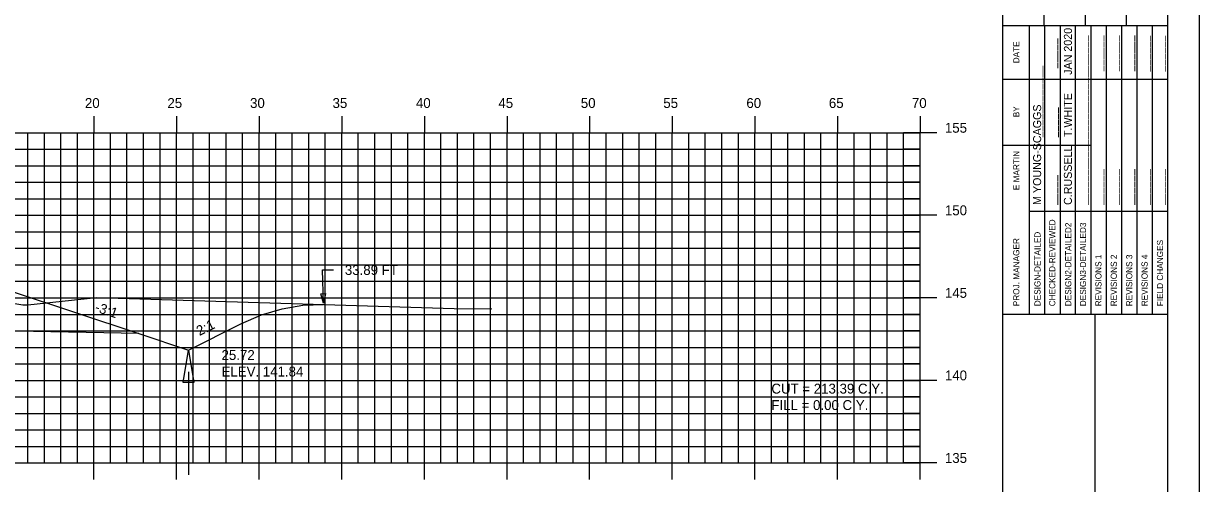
# Model space of a CAD drawing. Extents: x 1144751 to 1144921, y 608981 to 609091.
# Drawn here: x 1144849.4 to 1144920.5, y 609019.1 to 609047 of the extents above; entities that cross this region are included whole.
import ezdxf

# ---------------------------------------------------------------- set-up
doc = ezdxf.new("R2010")
doc.units = 0
for name, color, linetype in [('ANNOTATION', 7, 'Continuous'), ('BORDER', 7, 'Continuous'), ('D_Drainage_Ditch_Line', 7, 'Continuous'), ('D_Roadway_SlopeLines', 7, 'Continuous'), ('D_Roadway_SubGrade', 7, 'Continuous'), ('D_Text_Standard', 7, 'Continuous'), ('H_V ANNOTATION', 7, 'Continuous'), ('MAJOR', 7, 'Continuous'), ('MINOR', 7, 'Continuous'), ('PLOT BOUNDARY', 7, 'Continuous'), ('S_Roadway_Centerline', 7, 'Continuous')]:
    doc.layers.add(name, color=color, linetype=linetype)

msp = doc.modelspace()

# ---------------------------------------------------------------- linework, layer by layer
msp.add_lwpolyline([(1144816.245, 609030.888), (1144818.619, 609030.746), (1144822.619, 609030.906), (1144833.619, 609031.126), (1144844.619, 609030.906), (1144848.619, 609030.746), (1144856.342, 609028.171), (1144859.342, 609027.171), (1144862.514, 609028.757), (1144863.764, 609029.299), (1144865.014, 609029.675), (1144866.264, 609029.885), (1144867.514, 609029.928)])
at = {"layer": 'BORDER'}
for p, q in [((1144908.619, 608984.335), (1144908.619, 609089.335)), ((1144911.119, 609046.838), (1144911.119, 609055.485)), ((1144913.619, 609046.838), (1144913.619, 609055.485)), ((1144916.119, 609046.838), (1144916.119, 609055.485)), ((1144908.619, 609046.838), (1144918.619, 609046.838)), ((1144908.619, 609029.338), (1144918.619, 609029.338)), ((1144914.21, 608994.338), (1144914.21, 609029.338))]:
    msp.add_line(p, q, dxfattribs=at)
msp.add_lwpolyline([(1144758.619, 608984.335), (1144918.619, 608984.335), (1144918.619, 609089.335), (1144758.619, 609089.335)], close=True, dxfattribs=at)
for points in [[(1144910.234, 609043.588), (1144910.234, 609046.838)], [(1144911.167, 609029.341), (1144911.167, 609046.838)], [(1144912.098, 609046.838), (1144912.098, 609029.341)], [(1144913.03, 609029.341), (1144913.03, 609046.838)], [(1144913.962, 609029.341), (1144913.962, 609046.838)], [(1144914.893, 609029.341), (1144914.893, 609046.838)], [(1144915.825, 609029.341), (1144915.825, 609046.838)], [(1144916.757, 609029.341), (1144916.757, 609046.838)], [(1144917.688, 609029.341), (1144917.688, 609046.838)], [(1144910.235, 609029.341), (1144910.235, 609046.132)], [(1144908.619, 609043.588), (1144918.619, 609043.588)], [(1144908.619, 609039.588), (1144910.235, 609039.588)], [(1144910.234, 609039.588), (1144913.961, 609039.588)], [(1144910.234, 609035.588), (1144918.619, 609035.588)]]:
    msp.add_lwpolyline(points, dxfattribs=at)
at = {"layer": 'D_Drainage_Ditch_Line'}
msp.add_line((1144859.342, 609025.859), (1144859.342, 609019.616), dxfattribs=at)
msp.add_lwpolyline([(1144859.67, 609025.203), (1144859.014, 609025.203), (1144859.342, 609027.171)], close=True, dxfattribs=at)
at = {"layer": 'D_Roadway_SlopeLines'}
for points in [[(1144859.342, 609027.171), (1144862.514, 609028.757), (1144863.764, 609029.299), (1144865.014, 609029.675), (1144866.264, 609029.885), (1144867.514, 609029.928)], [(1144856.342, 609028.171), (1144859.342, 609027.171)]]:
    msp.add_lwpolyline(points, dxfattribs=at)
at = {"layer": 'D_Roadway_SubGrade'}
msp.add_lwpolyline([(1144844.619, 609030.489), (1144844.619, 609030.656), (1144848.619, 609030.496), (1144848.619, 609030.746), (1144848.619, 609030.746), (1144856.342, 609028.171), (1144844.619, 609028.406)], close=True, dxfattribs=at)
at = {"layer": 'D_Text_Standard'}
msp.add_lwpolyline([(1144867.514, 609030.007), (1144867.445, 609032.022), (1144868.125, 609032.022)], dxfattribs=at)
msp.add_lwpolyline([(1144867.514, 609030.007), (1144867.348, 609030.584), (1144867.639, 609030.594)], close=True, dxfattribs=at)
at = {"layer": 'MAJOR'}
for p, q in [((1144853.619, 609041.337), (1144853.619, 609040.335)), ((1144858.619, 609041.337), (1144858.619, 609040.335)), ((1144863.619, 609041.337), (1144863.619, 609040.335)), ((1144868.619, 609041.337), (1144868.619, 609040.335)), ((1144873.619, 609041.337), (1144873.619, 609040.335)), ((1144878.619, 609041.337), (1144878.619, 609040.335)), ((1144883.619, 609041.337), (1144883.619, 609040.335)), ((1144888.619, 609041.337), (1144888.619, 609040.335)), ((1144893.619, 609041.337), (1144893.619, 609040.335)), ((1144898.619, 609041.337), (1144898.619, 609040.335)), ((1144903.619, 609041.337), (1144903.619, 609040.335)), ((1144763.619, 609040.335), (1144903.619, 609040.335)), ((1144763.619, 609040.335), (1144903.619, 609040.335)), ((1144853.619, 609020.335), (1144853.619, 609040.335)), ((1144858.619, 609020.335), (1144858.619, 609040.335)), ((1144863.619, 609020.335), (1144863.619, 609040.335)), ((1144868.619, 609020.335), (1144868.619, 609040.335)), ((1144873.619, 609020.335), (1144873.619, 609040.335)), ((1144878.619, 609020.335), (1144878.619, 609040.335)), ((1144883.619, 609020.335), (1144883.619, 609040.335)), ((1144888.619, 609020.335), (1144888.619, 609040.335)), ((1144893.619, 609020.335), (1144893.619, 609040.335)), ((1144898.619, 609020.335), (1144898.619, 609040.335)), ((1144904.621, 609040.335), (1144902.617, 609040.335)), ((1144903.619, 609020.335), (1144903.619, 609040.335)), ((1144903.619, 609020.335), (1144903.619, 609040.335)), ((1144763.619, 609035.335), (1144903.619, 609035.335)), ((1144904.621, 609035.335), (1144902.617, 609035.335)), ((1144763.619, 609030.335), (1144903.619, 609030.335)), ((1144904.621, 609030.335), (1144902.617, 609030.335)), ((1144763.619, 609025.335), (1144903.619, 609025.335)), ((1144904.621, 609025.335), (1144902.617, 609025.335)), ((1144763.619, 609020.335), (1144903.619, 609020.335)), ((1144763.619, 609020.335), (1144903.619, 609020.335)), ((1144853.619, 609019.333), (1144853.619, 609020.335)), ((1144858.619, 609019.333), (1144858.619, 609020.335)), ((1144863.619, 609019.333), (1144863.619, 609020.335)), ((1144868.619, 609019.333), (1144868.619, 609020.335)), ((1144873.619, 609019.333), (1144873.619, 609020.335)), ((1144878.619, 609019.333), (1144878.619, 609020.335)), ((1144883.619, 609019.333), (1144883.619, 609020.335)), ((1144888.619, 609019.333), (1144888.619, 609020.335)), ((1144893.619, 609019.333), (1144893.619, 609020.335)), ((1144898.619, 609019.333), (1144898.619, 609020.335)), ((1144904.621, 609020.335), (1144902.617, 609020.335)), ((1144903.619, 609019.333), (1144903.619, 609020.335))]:
    msp.add_line(p, q, dxfattribs=at)
at = {"layer": 'MINOR'}
for p, q in [((1144849.619, 609020.335), (1144849.619, 609040.335)), ((1144850.619, 609020.335), (1144850.619, 609040.335)), ((1144851.619, 609020.335), (1144851.619, 609040.335)), ((1144852.619, 609020.335), (1144852.619, 609040.335)), ((1144854.619, 609020.335), (1144854.619, 609040.335)), ((1144855.619, 609020.335), (1144855.619, 609040.335)), ((1144856.619, 609020.335), (1144856.619, 609040.335)), ((1144857.619, 609020.335), (1144857.619, 609040.335)), ((1144859.619, 609020.335), (1144859.619, 609040.335)), ((1144860.619, 609020.335), (1144860.619, 609040.335)), ((1144861.619, 609020.335), (1144861.619, 609040.335)), ((1144862.619, 609020.335), (1144862.619, 609040.335)), ((1144864.619, 609020.335), (1144864.619, 609040.335)), ((1144865.619, 609020.335), (1144865.619, 609040.335)), ((1144866.619, 609020.335), (1144866.619, 609040.335)), ((1144867.619, 609020.335), (1144867.619, 609040.335)), ((1144869.619, 609020.335), (1144869.619, 609040.335)), ((1144870.619, 609020.335), (1144870.619, 609040.335)), ((1144871.619, 609020.335), (1144871.619, 609040.335)), ((1144872.619, 609020.335), (1144872.619, 609040.335)), ((1144874.619, 609020.335), (1144874.619, 609040.335)), ((1144875.619, 609020.335), (1144875.619, 609040.335)), ((1144876.619, 609020.335), (1144876.619, 609040.335)), ((1144877.619, 609020.335), (1144877.619, 609040.335)), ((1144879.619, 609020.335), (1144879.619, 609040.335)), ((1144880.619, 609020.335), (1144880.619, 609040.335)), ((1144881.619, 609020.335), (1144881.619, 609040.335)), ((1144882.619, 609020.335), (1144882.619, 609040.335)), ((1144884.619, 609020.335), (1144884.619, 609040.335)), ((1144885.619, 609020.335), (1144885.619, 609040.335)), ((1144886.619, 609020.335), (1144886.619, 609040.335)), ((1144887.619, 609020.335), (1144887.619, 609040.335)), ((1144889.619, 609020.335), (1144889.619, 609040.335)), ((1144890.619, 609020.335), (1144890.619, 609040.335)), ((1144891.619, 609020.335), (1144891.619, 609040.335)), ((1144892.619, 609020.335), (1144892.619, 609040.335)), ((1144894.619, 609020.335), (1144894.619, 609040.335)), ((1144895.619, 609020.335), (1144895.619, 609040.335)), ((1144896.619, 609020.335), (1144896.619, 609040.335)), ((1144897.619, 609020.335), (1144897.619, 609040.335)), ((1144899.619, 609020.335), (1144899.619, 609040.335)), ((1144900.619, 609020.335), (1144900.619, 609040.335)), ((1144901.619, 609020.335), (1144901.619, 609040.335)), ((1144902.619, 609020.335), (1144902.619, 609040.335)), ((1144763.619, 609039.335), (1144903.619, 609039.335)), ((1144903.619, 609039.335), (1144902.617, 609039.335)), ((1144763.619, 609038.335), (1144903.619, 609038.335)), ((1144903.619, 609038.335), (1144902.617, 609038.335)), ((1144763.619, 609037.335), (1144903.619, 609037.335)), ((1144903.619, 609037.335), (1144902.617, 609037.335)), ((1144763.619, 609036.335), (1144903.619, 609036.335)), ((1144903.619, 609036.335), (1144902.617, 609036.335)), ((1144763.619, 609034.335), (1144903.619, 609034.335)), ((1144903.619, 609034.335), (1144902.617, 609034.335)), ((1144763.619, 609033.335), (1144903.619, 609033.335)), ((1144903.619, 609033.335), (1144902.617, 609033.335)), ((1144763.619, 609032.335), (1144903.619, 609032.335)), ((1144903.619, 609032.335), (1144902.617, 609032.335)), ((1144763.619, 609031.335), (1144903.619, 609031.335)), ((1144903.619, 609031.335), (1144902.617, 609031.335)), ((1144763.619, 609029.335), (1144903.619, 609029.335)), ((1144903.619, 609029.335), (1144902.617, 609029.335)), ((1144763.619, 609028.335), (1144903.619, 609028.335)), ((1144903.619, 609028.335), (1144902.617, 609028.335)), ((1144763.619, 609027.335), (1144903.619, 609027.335)), ((1144903.619, 609027.335), (1144902.617, 609027.335)), ((1144763.619, 609026.335), (1144903.619, 609026.335)), ((1144903.619, 609026.335), (1144902.617, 609026.335)), ((1144763.619, 609024.335), (1144903.619, 609024.335)), ((1144903.619, 609024.335), (1144902.617, 609024.335)), ((1144763.619, 609023.335), (1144903.619, 609023.335)), ((1144903.619, 609023.335), (1144902.617, 609023.335)), ((1144763.619, 609022.335), (1144903.619, 609022.335)), ((1144903.619, 609022.335), (1144902.617, 609022.335)), ((1144763.619, 609021.335), (1144903.619, 609021.335)), ((1144903.619, 609021.335), (1144902.617, 609021.335))]:
    msp.add_line(p, q, dxfattribs=at)
at = {"layer": 'PLOT BOUNDARY'}
msp.add_lwpolyline([(1144750.526, 608981.276), (1144920.526, 608981.276), (1144920.526, 609091.276), (1144750.526, 609091.276)], close=True, dxfattribs=at)
at = {"layer": 'S_Roadway_Centerline'}
msp.add_lwpolyline([(1144783.338, 609031.937), (1144785.588, 609032.156), (1144803.411, 609031.709), (1144806.171, 609031.584), (1144812.1, 609030.451), (1144812.366, 609030.413), (1144812.487, 609030.445), (1144817.107, 609031.177), (1144819.29, 609031.161), (1144819.463, 609031.18), (1144820.262, 609031.19), (1144830.751, 609031.377), (1144840.894, 609030.911), (1144841.691, 609030.885), (1144841.859, 609030.863), (1144846.068, 609030.451), (1144846.347, 609030.396), (1144849.307, 609029.907), (1144849.614, 609029.914), (1144853.774, 609030.361), (1144875.416, 609029.679), (1144877.702, 609029.675)], dxfattribs=at)

# ---------------------------------------------------------------- texts
at = {"layer": 'ANNOTATION'}
for s, rotation, p in [('-3:1', 341.56521, (1144853.63, 609029.53)), ('2:1', 26.56505, (1144860.001, 609028.019))]:
    msp.add_text(s, height=0.6, rotation=rotation, dxfattribs=at).set_placement(p)
at = {"layer": 'BORDER'}
for s, height, p in [('JAN 2020', 0.4845, (1144912.805, 609043.843)), ('DATE', 0.3714, (1144909.623, 609044.544)), ('_____', 0.4845, (1144911.836, 609044.243)), ('______', 0.4845, (1144913.7, 609044.063)), ('______', 0.4845, (1144914.631, 609044.065)), ('______', 0.4845, (1144915.563, 609044.067)), ('______', 0.4845, (1144916.495, 609044.067)), ('______', 0.4845, (1144917.427, 609044.036)), ('______', 0.4845, (1144918.358, 609044.036)), ('____________', 0.48455, (1144910.942, 609040.073)), ('____________', 0.48455, (1144913.7, 609040.073)), ('T.WHITE', 0.4845, (1144912.805, 609040.073)), ('M YOUNG-SCAGGS', 0.48455, (1144910.942, 609035.961)), ('BY', 0.3714, (1144909.623, 609041.273)), ('_____', 0.4845, (1144911.874, 609040.073)), ('____________', 0.48455, (1144913.7, 609035.961)), ('E MARTIN', 0.3727, (1144909.623, 609036.855)), ('C.RUSSELL', 0.4845, (1144912.805, 609035.961)), ('_____', 0.4845, (1144911.836, 609035.961)), ('______', 0.4845, (1144914.631, 609035.961)), ('______', 0.4845, (1144915.563, 609035.961)), ('______', 0.4845, (1144916.495, 609035.961)), ('______', 0.4845, (1144917.427, 609035.961)), ('______', 0.4845, (1144918.358, 609035.961)), ('CHECKED-REVIEWED', 0.37275, (1144911.8, 609029.826)), ('DESIGN3-DETAILED3', 0.37275, (1144913.663, 609029.826)), ('DESIGN-DETAILED', 0.37275, (1144910.906, 609029.826)), ('DESIGN2-DETAILED2', 0.37275, (1144912.769, 609029.826)), ('PROJ. MANAGER', 0.37275, (1144909.623, 609029.826)), ('FIELD CHANGES', 0.37275, (1144918.322, 609029.826)), ('REVISIONS 1', 0.37275, (1144914.595, 609029.826)), ('REVISIONS 2', 0.37275, (1144915.527, 609029.826)), ('REVISIONS 3', 0.37275, (1144916.459, 609029.826)), ('REVISIONS 4', 0.37275, (1144917.39, 609029.826))]:
    msp.add_text(s, height=height, rotation=90, dxfattribs=at).set_placement(p)
at = {"layer": 'D_Text_Standard'}
for s, p in [('33.89 FT', (1144868.805, 609031.722)), ('25.72', (1144861.342, 609026.571)), ('ELEV. 141.84', (1144861.342, 609025.569)), ('CUT = 213.39 C.Y.', (1144894.619, 609024.535)), ('FILL = 0.00 C.Y.', (1144894.619, 609023.539))]:
    msp.add_text(s, height=0.6, dxfattribs=at).set_placement(p)
at = {"layer": 'H_V ANNOTATION'}
for s, p in [('20', (1144853.073, 609041.835)), ('25', (1144858.065, 609041.835)), ('30', (1144863.068, 609041.835)), ('35', (1144868.06, 609041.835)), ('40', (1144873.105, 609041.835)), ('45', (1144878.097, 609041.835)), ('50', (1144883.084, 609041.835)), ('55', (1144888.076, 609041.835)), ('60', (1144893.105, 609041.835)), ('65', (1144898.097, 609041.835)), ('70', (1144903.121, 609041.835)), ('155', (1144905.119, 609040.335)), ('150', (1144905.119, 609035.335)), ('145', (1144905.119, 609030.335)), ('140', (1144905.119, 609025.335)), ('135', (1144905.119, 609020.335))]:
    msp.add_text(s, height=0.6, dxfattribs=at).set_placement(p)

doc.saveas('drawing.dxf')
